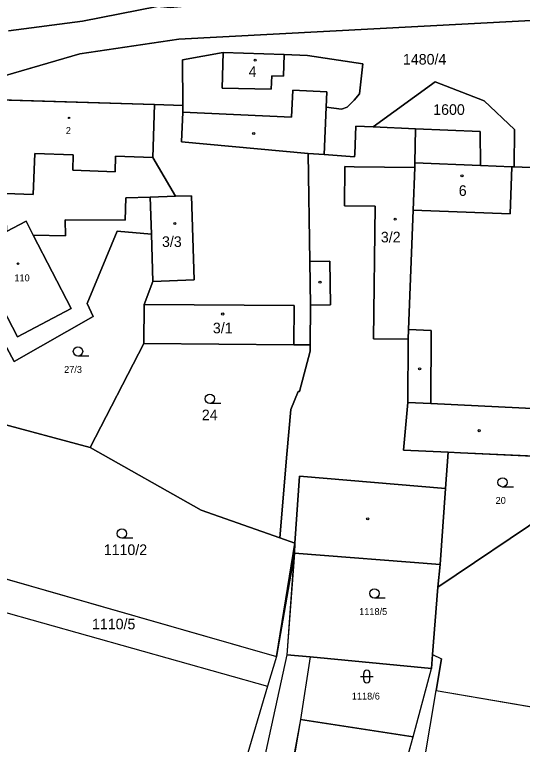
# Model space of a CAD drawing. Extents: x -760642 to -757221, y -1092371 to -1088855.
# Drawn here: x -759278.1 to -759196.6, y -1089899.5 to -1089782.4 of the extents above; entities that cross this region are included whole.
import ezdxf

# ---------------------------------------------------------------- set-up
doc = ezdxf.new("R2010")
doc.units = 0
for name, color, linetype in [('Vrstva 1', 7, 'Continuous'), ('Vrstva 18', 7, 'Continuous'), ('Vrstva 19', 7, 'Continuous'), ('Vrstva 25', 7, 'Continuous'), ('Vrstva 26', 7, 'Continuous'), ('Vrstva 27', 7, 'Continuous'), ('Vrstva 4', 7, 'Continuous')]:
    doc.layers.add(name, color=color, linetype=linetype)

msp = doc.modelspace()

# ---------------------------------------------------------------- linework, layer by layer
at = {"layer": 'Vrstva 1'}
for p, q in [((-759255.22, -1089781.14), (-759267.19, -1089783.47)), ((-759267.19, -1089783.47), (-759279.06, -1089785.04)), ((-759189.17, -1089783.09), (-759251.73, -1089786.4)), ((-759251.73, -1089786.4), (-759267.64, -1089788.76)), ((-759244.62, -1089788.55), (-759251.16, -1089789.68)), ((-759234.88, -1089788.87), (-759244.62, -1089788.55)), ((-759267.64, -1089788.76), (-759284.76, -1089793.72)), ((-759251.16, -1089789.68), (-759251.12, -1089797.02)), ((-759231.13, -1089789), (-759234.88, -1089788.87)), ((-759231.13, -1089789), (-759222.24, -1089790.35)), ((-759222.24, -1089790.35), (-759222.79, -1089795.14)), ((-759220.6, -1089800.47), (-759210.64, -1089793.23)), ((-759210.64, -1089793.23), (-759202.8, -1089796.29)), ((-759222.79, -1089795.14), (-759223.65, -1089796.18)), ((-759283.95, -1089796), (-759255.67, -1089796.88)), ((-759223.65, -1089796.18), (-759224.75, -1089797.29)), ((-759202.8, -1089796.29), (-759197.89, -1089800.9)), ((-759255.94, -1089805.37), (-759255.67, -1089796.88)), ((-759255.67, -1089796.88), (-759251.12, -1089797.02)), ((-759251.12, -1089797.02), (-759251.12, -1089798.07)), ((-759228.46, -1089804.91), (-759228.11, -1089797.31)), ((-759225.68, -1089797.59), (-759228.11, -1089797.31)), ((-759224.75, -1089797.29), (-759225.68, -1089797.59)), ((-759251.34, -1089802.87), (-759251.12, -1089798.07)), ((-759223.53, -1089804.8), (-759223.34, -1089800.35)), ((-759220.6, -1089800.47), (-759223.34, -1089800.35)), ((-759213.8, -1089800.76), (-759220.6, -1089800.47)), ((-759213.8, -1089800.76), (-759213.87, -1089806.24)), ((-759203.41, -1089801.2), (-759213.8, -1089800.76)), ((-759203.38, -1089806.65), (-759203.41, -1089801.2)), ((-759197.89, -1089800.9), (-759197.98, -1089806.87)), ((-759251.34, -1089802.87), (-759231.03, -1089804.73)), ((-759228.46, -1089804.91), (-759231.03, -1089804.73)), ((-759231.03, -1089804.73), (-759230.75, -1089822.06)), ((-759223.55, -1089805.25), (-759228.46, -1089804.91)), ((-759223.53, -1089804.8), (-759223.55, -1089805.25)), ((-759255.94, -1089805.37), (-759252.31, -1089811.59)), ((-759214.17, -1089813.83), (-759213.9, -1089806.98)), ((-759213.9, -1089806.98), (-759213.87, -1089806.24)), ((-759203.38, -1089806.65), (-759198.34, -1089806.85)), ((-759198.34, -1089806.85), (-759197.98, -1089806.87)), ((-759197.98, -1089806.87), (-759194.09, -1089807.03)), ((-759260.27, -1089811.85), (-759260.34, -1089815.44)), ((-759256.34, -1089811.72), (-759260.27, -1089811.85)), ((-759252.31, -1089811.59), (-759256.34, -1089811.72)), ((-759256.34, -1089811.72), (-759256.15, -1089817.66)), ((-759249.72, -1089811.51), (-759252.31, -1089811.59)), ((-759249.29, -1089824.98), (-759249.72, -1089811.51)), ((-759214.93, -1089832.99), (-759214.17, -1089813.83)), ((-759260.34, -1089815.44), (-759269.97, -1089815.36)), ((-759269.92, -1089817.92), (-759269.97, -1089815.36)), ((-759279.39, -1089817.25), (-759276.25, -1089815.59)), ((-759276.25, -1089815.59), (-759275.1, -1089817.81)), ((-759275.1, -1089817.81), (-759269.01, -1089829.58)), ((-759275.1, -1089817.81), (-759269.92, -1089817.92)), ((-759261.62, -1089817.21), (-759266.47, -1089828.77)), ((-759256.15, -1089817.66), (-759261.62, -1089817.21)), ((-759256.15, -1089817.66), (-759255.9, -1089825.28)), ((-759277.64, -1089834.15), (-759284.89, -1089820.16)), ((-759230.75, -1089822.06), (-759230.63, -1089829.06)), ((-759255.9, -1089825.28), (-759257.34, -1089828.93)), ((-759255.9, -1089825.28), (-759249.29, -1089824.98)), ((-759269.01, -1089829.58), (-759277.64, -1089834.15)), ((-759266.47, -1089828.77), (-759265.47, -1089830.86)), ((-759257.34, -1089828.93), (-759257.39, -1089835.23)), ((-759230.63, -1089829.06), (-759230.69, -1089835.45)), ((-759265.47, -1089830.86), (-759278.18, -1089838.12)), ((-759214.93, -1089832.99), (-759214.94, -1089834.52)), ((-759257.39, -1089835.23), (-759265.97, -1089851.91)), ((-759257.39, -1089835.23), (-759233.29, -1089835.43)), ((-759233.29, -1089835.43), (-759230.69, -1089835.45)), ((-759230.69, -1089835.45), (-759230.7, -1089836.46)), ((-759214.94, -1089834.52), (-759215.04, -1089844.69)), ((-759230.7, -1089836.46), (-759232.4, -1089842.91)), ((-759232.62, -1089842.91), (-759233.79, -1089845.82)), ((-759232.62, -1089842.91), (-759232.4, -1089842.91)), ((-759215.04, -1089844.69), (-759215.71, -1089852.31)), ((-759233.79, -1089845.82), (-759234.45, -1089852.95)), ((-759281.18, -1089847.83), (-759265.97, -1089851.91)), ((-759265.97, -1089851.91), (-759248.15, -1089861.95)), ((-759234.45, -1089852.95), (-759235.54, -1089866.4)), ((-759215.71, -1089852.31), (-759208.57, -1089852.65)), ((-759209, -1089858.46), (-759208.57, -1089852.65)), ((-759208.57, -1089852.65), (-759206.56, -1089852.74)), ((-759206.56, -1089852.74), (-759192.26, -1089853.42)), ((-759209.83, -1089870.65), (-759209, -1089858.46)), ((-759248.15, -1089861.95), (-759235.54, -1089866.4)), ((-759192.7, -1089862.53), (-759210.19, -1089874.31)), ((-759235.54, -1089866.4), (-759233.14, -1089867.25)), ((-759233.14, -1089867.25), (-759233.18, -1089868.87)), ((-759233.18, -1089868.87), (-759236.1, -1089885.41)), ((-759233.18, -1089868.87), (-759234.41, -1089885.19)), ((-759233.18, -1089868.87), (-759209.83, -1089870.65)), ((-759286.99, -1089870.84), (-759236.1, -1089885.41)), ((-759209.83, -1089870.65), (-759210.19, -1089874.31)), ((-759210.19, -1089874.31), (-759211.05, -1089885.12)), ((-759287.57, -1089876.11), (-759237.54, -1089890.17)), ((-759234.41, -1089885.19), (-759240.43, -1089912.67)), ((-759236.1, -1089885.41), (-759237.54, -1089890.17)), ((-759230.7, -1089885.5), (-759234.41, -1089885.19)), ((-759230.7, -1089885.5), (-759232.25, -1089895.53)), ((-759211.23, -1089887.35), (-759230.7, -1089885.5)), ((-759211.05, -1089885.12), (-759211.23, -1089887.35)), ((-759211.05, -1089885.12), (-759209.61, -1089885.8)), ((-759210.46, -1089890.87), (-759209.61, -1089885.8)), ((-759214.17, -1089898.33), (-759211.23, -1089887.35)), ((-759237.54, -1089890.17), (-759242.76, -1089907.78)), ((-759216.56, -1089927.27), (-759210.46, -1089890.87)), ((-759210.46, -1089890.87), (-759175.58, -1089896.9)), ((-759232.25, -1089895.53), (-759233.18, -1089900.74)), ((-759232.25, -1089895.53), (-759214.17, -1089898.33)), ((-759222.04, -1089926.62), (-759214.17, -1089898.33))]:
    msp.add_line(p, q, dxfattribs=at)
at = {"layer": 'Vrstva 25'}
for p, q in [((-759266.18, -1089837.23), (-759267.93, -1089837.23)), ((-759245.03, -1089844.82), (-759246.78, -1089844.82)), ((-759198.07, -1089858.24), (-759199.82, -1089858.24)), ((-759259.14, -1089866.45), (-759260.89, -1089866.45)), ((-759218.63, -1089876.07), (-759220.38, -1089876.07)), ((-759222.1, -1089889.14), (-759222.1, -1089888.14)), ((-759221.1, -1089889.14), (-759221.1, -1089888.14)), ((-759222.6, -1089888.64), (-759220.6, -1089888.64))]:
    msp.add_line(p, q, dxfattribs=at)
for centre, radius in [((-759239.5, -1089789.76), 0.175), ((-759269.35, -1089799.02), 0.117), ((-759239.74, -1089801.52), 0.175), ((-759206.33, -1089808.31), 0.175), ((-759217.05, -1089815.26), 0.175), ((-759252.4, -1089815.95), 0.175), ((-759277.55, -1089822.41), 0.117), ((-759229.12, -1089825.37), 0.175), ((-759244.71, -1089830.48), 0.175), ((-759267.93, -1089836.48), 0.75), ((-759213.13, -1089839.28), 0.175), ((-759246.78, -1089844.07), 0.75), ((-759203.58, -1089849.21), 0.175), ((-759199.82, -1089857.49), 0.75), ((-759221.46, -1089863.35), 0.175), ((-759260.89, -1089865.7), 0.75), ((-759220.38, -1089875.32), 0.75)]:
    msp.add_circle(centre, radius, dxfattribs=at)
for centre, start, end in [((-759221.6, -1089888.14), 0, 180), ((-759221.6, -1089889.14), 180, 0)]:
    msp.add_arc(centre, 0.5, start, end, dxfattribs=at)
at = {"layer": 'Vrstva 26'}
for points in [[(-759279.06, -1089785.04), (-759267.19, -1089783.47), (-759255.22, -1089781.14), (-759274.75, -1089779.3), (-759274.99, -1089777.55), (-759275.76, -1089771.78), (-759275.82, -1089771.26), (-759282.31, -1089771.47)], [(-759147.975, -1089779.722), (-759154.89, -1089778.9), (-759163.35, -1089777.67), (-759185.67, -1089777.61), (-759187.18, -1089777.61), (-759188.03, -1089777.62), (-759195.92, -1089779.58), (-759197.325, -1089779.382), (-759208.76, -1089777.77), (-759230.9, -1089777.93), (-759235.09, -1089779.66), (-759253.14, -1089781.34), (-759255.22, -1089781.14), (-759267.19, -1089783.47), (-759279.06, -1089785.04)], [(-759313.165, -1089810.283), (-759304.6, -1089803.62), (-759296.53, -1089798.79), (-759284.76, -1089793.72), (-759267.64, -1089788.76), (-759251.73, -1089786.4), (-759189.17, -1089783.09), (-759183.79, -1089782.45), (-759175.61, -1089783.69), (-759171.98, -1089784.24), (-759159.99, -1089785.24), (-759148.715, -1089787.512)], [(-759195.39, -1089793.75), (-759189.3, -1089793.71), (-759183.33, -1089793.67), (-759189.17, -1089783.09), (-759251.73, -1089786.4), (-759267.64, -1089788.76), (-759284.76, -1089793.72)], [(-759283.95, -1089796), (-759255.67, -1089796.88), (-759251.12, -1089797.02), (-759251.16, -1089789.68), (-759244.62, -1089788.55), (-759234.88, -1089788.87), (-759231.13, -1089789), (-759222.24, -1089790.35), (-759222.79, -1089795.14), (-759223.65, -1089796.18), (-759224.75, -1089797.29), (-759225.68, -1089797.59), (-759228.11, -1089797.31), (-759228.46, -1089804.91), (-759223.55, -1089805.25), (-759223.53, -1089804.8), (-759223.34, -1089800.35), (-759220.6, -1089800.47), (-759210.64, -1089793.23), (-759202.8, -1089796.29), (-759197.89, -1089800.9), (-759197.98, -1089806.87), (-759194.09, -1089807.03)], [(-759233.49, -1089794.59), (-759227.99, -1089794.84), (-759228.11, -1089797.31), (-759225.68, -1089797.59), (-759224.75, -1089797.29), (-759223.65, -1089796.18), (-759222.79, -1089795.14), (-759222.24, -1089790.35), (-759231.13, -1089789), (-759234.88, -1089788.87), (-759234.99, -1089792.31), (-759236.86, -1089792.25), (-759236.93, -1089794.42), (-759244.81, -1089794.24), (-759244.62, -1089788.55), (-759251.16, -1089789.68), (-759251.12, -1089797.02), (-759251.12, -1089798.07), (-759233.69, -1089798.88), (-759233.49, -1089794.59)], [(-759244.62, -1089788.55), (-759244.81, -1089794.24), (-759236.93, -1089794.42), (-759236.86, -1089792.25), (-759234.99, -1089792.31), (-759234.88, -1089788.87), (-759244.62, -1089788.55)], [(-759197.98, -1089806.87), (-759197.89, -1089800.9), (-759202.8, -1089796.29), (-759210.64, -1089793.23), (-759220.6, -1089800.47), (-759213.8, -1089800.76), (-759203.41, -1089801.2), (-759203.38, -1089806.65), (-759198.34, -1089806.85), (-759197.98, -1089806.87)], [(-759251.12, -1089798.07), (-759251.34, -1089802.87), (-759231.03, -1089804.73), (-759228.46, -1089804.91), (-759228.11, -1089797.31), (-759227.99, -1089794.84), (-759233.49, -1089794.59), (-759233.69, -1089798.88), (-759251.12, -1089798.07)], [(-759275.1, -1089817.81), (-759269.01, -1089829.58), (-759277.64, -1089834.15), (-759284.89, -1089820.16), (-759279.39, -1089817.25), (-759279.56, -1089811.16), (-759284.45, -1089811), (-759284.25, -1089804.39), (-759283.95, -1089796), (-759297.29, -1089802.97), (-759279.37, -1089835.93), (-759278.18, -1089838.12), (-759265.47, -1089830.86), (-759266.47, -1089828.77), (-759261.62, -1089817.21), (-759256.15, -1089817.66), (-759256.34, -1089811.72), (-759260.27, -1089811.85), (-759260.34, -1089815.44), (-759269.97, -1089815.36), (-759269.92, -1089817.92), (-759275.1, -1089817.81)], [(-759261.89, -1089805.17), (-759255.94, -1089805.37), (-759255.67, -1089796.88), (-759283.95, -1089796), (-759284.25, -1089804.39), (-759284.45, -1089811), (-759279.56, -1089811.16), (-759275.1, -1089811.31), (-759274.88, -1089804.71), (-759268.68, -1089804.92), (-759268.77, -1089807.42), (-759261.98, -1089807.65), (-759261.89, -1089805.17)], [(-759230.63, -1089829.06), (-759230.75, -1089822.06), (-759231.03, -1089804.73), (-759251.34, -1089802.87), (-759251.12, -1089798.07), (-759251.12, -1089797.02), (-759255.67, -1089796.88), (-759255.94, -1089805.37), (-759252.31, -1089811.59), (-759249.72, -1089811.51), (-759249.29, -1089824.98), (-759255.9, -1089825.28), (-759257.34, -1089828.93), (-759233.24, -1089829.13), (-759233.29, -1089835.43), (-759230.69, -1089835.45), (-759230.63, -1089829.06)], [(-759223.62, -1089806.85), (-759213.9, -1089806.98), (-759213.87, -1089806.24), (-759213.8, -1089800.76), (-759220.6, -1089800.47), (-759223.34, -1089800.35), (-759223.53, -1089804.8), (-759223.55, -1089805.25), (-759228.46, -1089804.91), (-759231.03, -1089804.73), (-759230.75, -1089822.06), (-759227.55, -1089822.01), (-759227.43, -1089829.01), (-759230.63, -1089829.06), (-759230.69, -1089835.45), (-759230.7, -1089836.46), (-759232.4, -1089842.91), (-759232.62, -1089842.91), (-759233.79, -1089845.82), (-759234.45, -1089852.95), (-759235.54, -1089866.4), (-759233.14, -1089867.25), (-759232.38, -1089856.5), (-759209, -1089858.46), (-759208.57, -1089852.65), (-759215.71, -1089852.31), (-759215.04, -1089844.69), (-759214.94, -1089834.52), (-759220.52, -1089834.44), (-759220.24, -1089813.2), (-759225.19, -1089813.13), (-759225.1, -1089806.83), (-759223.62, -1089806.85)], [(-759213.87, -1089806.24), (-759203.38, -1089806.65), (-759203.41, -1089801.2), (-759213.8, -1089800.76), (-759213.87, -1089806.24)], [(-759261.89, -1089805.17), (-759261.98, -1089807.65), (-759268.77, -1089807.42), (-759268.68, -1089804.92), (-759274.88, -1089804.71), (-759275.1, -1089811.31), (-759279.56, -1089811.16), (-759279.39, -1089817.25), (-759276.25, -1089815.59), (-759275.1, -1089817.81), (-759269.92, -1089817.92), (-759269.97, -1089815.36), (-759260.34, -1089815.44), (-759260.27, -1089811.85), (-759256.34, -1089811.72), (-759252.31, -1089811.59), (-759255.94, -1089805.37), (-759261.89, -1089805.17)], [(-759220.52, -1089834.44), (-759214.94, -1089834.52), (-759214.93, -1089832.99), (-759214.17, -1089813.83), (-759213.9, -1089806.98), (-759223.62, -1089806.85), (-759225.1, -1089806.83), (-759225.19, -1089813.13), (-759220.24, -1089813.2), (-759220.52, -1089834.44)], [(-759198.34, -1089806.85), (-759198.58, -1089814.41), (-759214.17, -1089813.83), (-759214.93, -1089832.99), (-759211.28, -1089833.14), (-759211.34, -1089844.86), (-759192.9, -1089845.73), (-759193.11, -1089821.64), (-759193.16, -1089815.67), (-759194.09, -1089807.03), (-759197.98, -1089806.87), (-759198.34, -1089806.85)], [(-759213.9, -1089806.98), (-759214.17, -1089813.83), (-759198.58, -1089814.41), (-759198.34, -1089806.85), (-759203.38, -1089806.65), (-759213.87, -1089806.24), (-759213.9, -1089806.98)], [(-759255.9, -1089825.28), (-759249.29, -1089824.98), (-759249.72, -1089811.51), (-759252.31, -1089811.59), (-759256.34, -1089811.72), (-759256.15, -1089817.66), (-759255.9, -1089825.28)], [(-759275.1, -1089817.81), (-759276.25, -1089815.59), (-759279.39, -1089817.25), (-759284.89, -1089820.16), (-759277.64, -1089834.15), (-759269.01, -1089829.58), (-759275.1, -1089817.81)], [(-759279.37, -1089835.93), (-759285.44, -1089839.29), (-759282.01, -1089845.41), (-759281.19, -1089846.87), (-759281.18, -1089847.83), (-759265.97, -1089851.91), (-759257.39, -1089835.23), (-759257.34, -1089828.93), (-759255.9, -1089825.28), (-759256.15, -1089817.66), (-759261.62, -1089817.21), (-759266.47, -1089828.77), (-759265.47, -1089830.86), (-759278.18, -1089838.12), (-759279.37, -1089835.93)], [(-759227.43, -1089829.01), (-759227.55, -1089822.01), (-759230.75, -1089822.06), (-759230.63, -1089829.06), (-759227.43, -1089829.01)], [(-759233.29, -1089835.43), (-759233.24, -1089829.13), (-759257.34, -1089828.93), (-759257.39, -1089835.23), (-759233.29, -1089835.43)], [(-759211.34, -1089844.86), (-759211.28, -1089833.14), (-759214.93, -1089832.99), (-759214.94, -1089834.52), (-759215.04, -1089844.69), (-759211.34, -1089844.86)], [(-759230.69, -1089835.45), (-759233.29, -1089835.43), (-759257.39, -1089835.23), (-759265.97, -1089851.91), (-759248.15, -1089861.95), (-759235.54, -1089866.4), (-759234.45, -1089852.95), (-759233.79, -1089845.82), (-759232.62, -1089842.91), (-759232.4, -1089842.91), (-759230.7, -1089836.46), (-759230.69, -1089835.45)], [(-759211.34, -1089844.86), (-759215.04, -1089844.69), (-759215.71, -1089852.31), (-759208.57, -1089852.65), (-759206.56, -1089852.74), (-759192.26, -1089853.42), (-759191.9, -1089845.78), (-759192.9, -1089845.73), (-759211.34, -1089844.86)], [(-759283.89, -1089854.99), (-759286.99, -1089870.84), (-759236.1, -1089885.41), (-759233.18, -1089868.87), (-759233.14, -1089867.25), (-759235.54, -1089866.4), (-759248.15, -1089861.95), (-759265.97, -1089851.91), (-759281.18, -1089847.83), (-759281.19, -1089846.87), (-759282.01, -1089845.41), (-759283.89, -1089854.99)], [(-759192.7, -1089862.53), (-759192.26, -1089853.42), (-759206.56, -1089852.74), (-759208.57, -1089852.65), (-759209, -1089858.46), (-759209.83, -1089870.65), (-759210.19, -1089874.31), (-759192.7, -1089862.53)], [(-759232.38, -1089856.5), (-759233.14, -1089867.25), (-759233.18, -1089868.87), (-759209.83, -1089870.65), (-759209, -1089858.46), (-759232.38, -1089856.5)], [(-759167.54, -1089864.99), (-759192.7, -1089862.53), (-759210.19, -1089874.31), (-759211.05, -1089885.12), (-759209.61, -1089885.8), (-759210.46, -1089890.87), (-759175.58, -1089896.9), (-759167.54, -1089864.99)], [(-759230.7, -1089885.5), (-759211.23, -1089887.35), (-759211.05, -1089885.12), (-759210.19, -1089874.31), (-759209.83, -1089870.65), (-759233.18, -1089868.87), (-759234.41, -1089885.19), (-759230.7, -1089885.5)], [(-759211.23, -1089887.35), (-759230.7, -1089885.5), (-759232.25, -1089895.53), (-759214.17, -1089898.33), (-759211.23, -1089887.35)], [(-759233.34, -1089901.75), (-759234.51, -1089908.62), (-759236.58, -1089920.99), (-759236.86, -1089925.63), (-759238.06, -1089945.94), (-759228.14, -1089947.36), (-759222.04, -1089926.62), (-759214.17, -1089898.33), (-759232.25, -1089895.53), (-759233.18, -1089900.74), (-759233.34, -1089901.75)]]:
    msp.add_lwpolyline(points, dxfattribs=at)
at = {"layer": 'Vrstva 27'}
msp.add_lwpolyline([(-759286.99, -1089870.84), (-759236.1, -1089885.41), (-759233.14, -1089867.25), (-759234.41, -1089885.19), (-759230.7, -1089885.5), (-759232.25, -1089895.53), (-759236.58, -1089920.99), (-759238.06, -1089945.94), (-759228.14, -1089947.36), (-759222.04, -1089926.62), (-759214.17, -1089898.33), (-759211.23, -1089887.35), (-759211.05, -1089885.12), (-759209.61, -1089885.8), (-759210.46, -1089890.87), (-759175.58, -1089896.9), (-759167.54, -1089864.99), (-759164.51, -1089865.15), (-759165.99, -1089872.4), (-759090.65, -1089878.08)], dxfattribs=at)
at = {"layer": 'Vrstva 4'}
for p, q in [((-759244.81, -1089794.24), (-759244.62, -1089788.55)), ((-759234.88, -1089788.87), (-759234.99, -1089792.31)), ((-759236.86, -1089792.25), (-759236.93, -1089794.42)), ((-759234.99, -1089792.31), (-759236.86, -1089792.25)), ((-759236.93, -1089794.42), (-759244.81, -1089794.24)), ((-759233.49, -1089794.59), (-759233.69, -1089798.88)), ((-759227.99, -1089794.84), (-759233.49, -1089794.59)), ((-759228.11, -1089797.31), (-759227.99, -1089794.84)), ((-759233.69, -1089798.88), (-759251.12, -1089798.07)), ((-759275.1, -1089811.31), (-759274.88, -1089804.71)), ((-759274.88, -1089804.71), (-759268.68, -1089804.92)), ((-759268.68, -1089804.92), (-759268.77, -1089807.42)), ((-759261.98, -1089807.65), (-759261.89, -1089805.17)), ((-759261.89, -1089805.17), (-759255.94, -1089805.37)), ((-759225.19, -1089813.13), (-759225.1, -1089806.83)), ((-759223.62, -1089806.85), (-759225.1, -1089806.83)), ((-759213.9, -1089806.98), (-759223.62, -1089806.85)), ((-759213.87, -1089806.24), (-759203.38, -1089806.65)), ((-759198.34, -1089806.85), (-759198.58, -1089814.41)), ((-759268.77, -1089807.42), (-759261.98, -1089807.65)), ((-759279.56, -1089811.16), (-759275.1, -1089811.31)), ((-759220.24, -1089813.2), (-759225.19, -1089813.13)), ((-759220.52, -1089834.44), (-759220.24, -1089813.2)), ((-759214.17, -1089813.83), (-759198.58, -1089814.41)), ((-759227.55, -1089822.01), (-759230.75, -1089822.06)), ((-759227.43, -1089829.01), (-759227.55, -1089822.01)), ((-759233.24, -1089829.13), (-759257.34, -1089828.93)), ((-759233.24, -1089829.13), (-759233.29, -1089835.43)), ((-759230.63, -1089829.06), (-759227.43, -1089829.01)), ((-759211.28, -1089833.14), (-759214.93, -1089832.99)), ((-759211.28, -1089833.14), (-759211.34, -1089844.86)), ((-759214.94, -1089834.52), (-759220.52, -1089834.44)), ((-759215.04, -1089844.69), (-759211.34, -1089844.86)), ((-759211.34, -1089844.86), (-759192.9, -1089845.73)), ((-759232.38, -1089856.5), (-759233.14, -1089867.25)), ((-759209, -1089858.46), (-759232.38, -1089856.5))]:
    msp.add_line(p, q, dxfattribs=at)

# ---------------------------------------------------------------- texts
at = {"layer": 'Vrstva 18'}
for s, height, p in [('1480/4', 1.7, (-759215.8, -1089790.46)), ('1600', 1.7, (-759210.942, -1089798.53)), ('27/3', 1.1, (-759270.157, -1089839.93)), ('24', 1.7, (-759248.061, -1089847.52)), ('20', 1.1, (-759200.938, -1089860.94)), ('1110/2', 1.7, (-759263.794, -1089869.15)), ('1118/5', 1.1, (-759222.827, -1089878.77)), ('1110/5', 1.7, (-759265.681, -1089881.07)), ('1118/6', 1.1, (-759224.006, -1089892.34))]:
    msp.add_text(s, height=height, dxfattribs=at).set_placement(p)
at = {"layer": 'Vrstva 19'}
for s, height, p in [('4', 1.7, (-759240.558, -1089792.43)), ('2', 1.1, (-759269.884, -1089801.59)), ('6', 1.7, (-759206.848, -1089811.53)), ('3/2', 1.7, (-759219.344, -1089818.99)), ('3/3', 1.7, (-759254.456, -1089819.72)), ('110', 1.1, (-759278.132, -1089825.23)), ('3/1', 1.7, (-759246.292, -1089833.58))]:
    msp.add_text(s, height=height, dxfattribs=at).set_placement(p)

doc.saveas('drawing.dxf')
